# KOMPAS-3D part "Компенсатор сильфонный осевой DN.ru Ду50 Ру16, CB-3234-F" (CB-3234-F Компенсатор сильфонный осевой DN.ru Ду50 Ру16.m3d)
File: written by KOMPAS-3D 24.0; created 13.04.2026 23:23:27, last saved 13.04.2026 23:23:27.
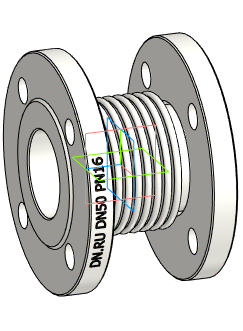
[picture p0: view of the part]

Document properties: Автор: DN.RU; Полное имя файла: D:\PROJECT CAD\DN.RU\...198(ACTUALE). CB-3234-F Компенсатор сильфонный осевой DN.ru\Исходники\DN50\CB-3234-F Компенсатор сильфонный осевой DN.ru Ду50 Ру16.m3d

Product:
- Body: Твердое тело1  | qty 1
    Масса: 6.006597
- Part/product: Компенсатор сильфонный осевой DN.ru Ду50 Ру16  | designation CB-3234-F
    Масса: 5
    Раздел спецификации: Прочие изделия
    Комментарий: D140-02113
    Примечание: D140-02113
    additional columns: Типовые

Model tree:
1. Твердое тело1  (labels: Твердое тело1)

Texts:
  CB-3234-F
